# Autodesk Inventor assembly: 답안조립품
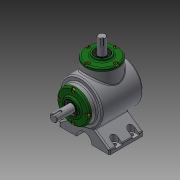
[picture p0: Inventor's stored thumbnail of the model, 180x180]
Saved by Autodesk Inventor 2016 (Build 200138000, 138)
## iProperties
Created: 2017-04
Part Number: 답안조립품
Material: 일반
Document SubType Name: Assembly
Designer: H
Author: H
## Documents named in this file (14)
- C:\Users\CAMTIC\Desktop\470407V1025\답안조립품.iam
- C:\Users\CAMTIC\Desktop\470407V1025\1-본체.ipt
- C:\Users\CAMTIC\Desktop\470407V1025\메인 베벨기어.ipt
- C:\Users\CAMTIC\Desktop\470407V1025\메인 축.ipt
- 메인 축.ipt
- C:\Users\CAMTIC\Desktop\470407V1025\베어링 6203.ipt
- C:\Users\CAMTIC\Desktop\470407V1025\볼트 M4.ipt
- C:\Users\CAMTIC\Desktop\470407V1025\서브 베벨기어.ipt
- C:\Users\CAMTIC\Desktop\470407V1025\서브 축.ipt
- 서브 축.ipt
- C:\Users\CAMTIC\Desktop\470407V1025\오일실 17 32 8.ipt
- C:\Users\CAMTIC\Desktop\470407V1025\커버.ipt
- C:\Users\CAMTIC\Desktop\470407V1025\키 4x4.ipt
- C:\Users\CAMTIC\Desktop\470407V1025\키 5x5.ipt
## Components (1 placed, 1 different names)
1. 1-본체:1 — 플러쉬:1, 플러쉬:2, 플러쉬:3
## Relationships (3: Flush 3)
- 플러쉬:1 [Flush]: 1-본체:1
- 플러쉬:2 [Flush]: 1-본체:1
- 플러쉬:3 [Flush]: 1-본체:1
